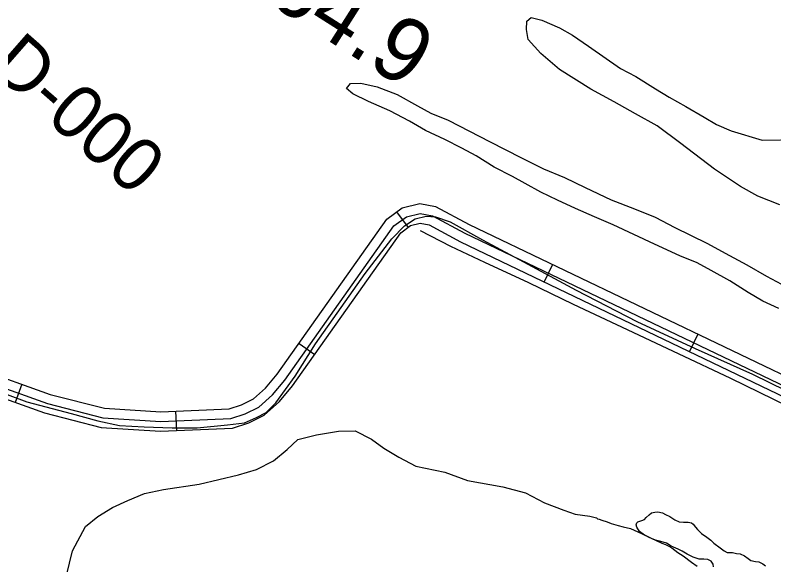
# Model space of a CAD drawing. Extents: x 3361039 to 3398939, y 576572 to 602007.
# Drawn here: x 3386835 to 3388012, y 594802 to 595655 of the extents above; entities that cross this region are included whole.
import ezdxf

# ---------------------------------------------------------------- set-up
doc = ezdxf.new("R2010")
doc.units = 0
for name, color, linetype in [('V-DTCH-CNTR', 7, 'Continuous'), ('V-RIVR-RANG-IDEN', 7, 'Continuous'), ('V-ROAD-CNTR', 7, 'Continuous'), ('V-SITE-VEGE', 7, 'Continuous'), ('V-SURV-IDEN', 7, 'Continuous'), ('V-TOPO-SHOR', 7, 'Continuous')]:
    doc.layers.add(name, color=color, linetype=linetype)

msp = doc.modelspace()

# ---------------------------------------------------------------- linework, layer by layer
at = {"layer": 'V-DTCH-CNTR'}
for points in [[(3386787.3, 595079), (3386852.9, 595054.6), (3386921.8, 595036.6), (3386963.3, 595025), (3386997, 595018.1), (3387035, 595015.7), (3387078.4, 595014.4), (3387117.4, 595014.4), (3387164.5, 595019), (3387190.8, 595022.3), (3387209.7, 595030.3), (3387224.6, 595038.3), (3387239.5, 595053.1), (3387269.6, 595094.5), (3387301.1, 595144.6), (3387340.7, 595201.1), (3387377.9, 595254.2), (3387419.6, 595307.9), (3387439.2, 595328.1), (3387455.6, 595339.1), (3387472.6, 595343.2), (3387487.3, 595341.9), (3387509.8, 595334), (3387560.3, 595306.4), (3387623.6, 595272.3), (3387705.5, 595228.1), (3387799.7, 595179.3), (3387889.9, 595137.7), (3387979.1, 595097.5)], [(3387979.1, 595097.5), (3388056.2, 595060), (3388142.7, 595016.8), (3388245.8, 594973.9), (3388341.5, 594936.1)]]:
    msp.add_lwpolyline(points, dxfattribs=at)
at = {"layer": 'V-ROAD-CNTR'}
for p, q in [((3387426.7, 595349.5), (3387444.7, 595325.5)), ((3387668.8, 595268), (3387655.8, 595240.9)), ((3387894.2, 595159.9), (3387881.2, 595132.8)), ((3387275.6, 595145.5), (3387300.1, 595128.2)), ((3386845.4, 595082.1), (3386835.2, 595053.8)), ((3387083.9, 595040.1), (3387085.2, 595010.2))]:
    msp.add_line(p, q, dxfattribs=at)
for points in [[(3386327.6, 595267.7), (3386889.4, 595066.3), (3386973.4, 595044.7), (3387061, 595039.2), (3387166.9, 595043.6), (3387186, 595049.9), (3387204.7, 595059.1), (3387223.6, 595076.1), (3387241.7, 595097.7), (3387411.8, 595338.4), (3387435.5, 595356.1), (3387462.9, 595362.6), (3387487.4, 595358), (3387539.5, 595330), (3388219.5, 595003.8)], [(3386322.6, 595253.5), (3386885, 595051.9), (3386971.1, 595029.8), (3387060.9, 595024.2), (3387169.6, 595028.7), (3387191.7, 595036), (3387213.2, 595046.5), (3387234.4, 595065.7), (3387253.6, 595088.5), (3387422.7, 595327.8), (3387442, 595342.2), (3387463.3, 595347.3), (3387482.3, 595343.6), (3387532.7, 595316.6), (3388213.1, 594990.3)], [(3386317.5, 595239.4), (3386880.6, 595037.6), (3386968.7, 595015), (3387060.7, 595009.2), (3387172.3, 595013.8), (3387197.4, 595022.1), (3387221.6, 595034), (3387245.2, 595055.2), (3387265.5, 595079.3), (3387433.5, 595317.2), (3387448.5, 595328.3), (3387463.6, 595331.9), (3387477.3, 595329.3), (3387525.9, 595303.2), (3388206.6, 594976.8)]]:
    msp.add_lwpolyline(points, dxfattribs=at)
at = {"layer": 'V-SITE-VEGE'}
for points in [[(3388021.1, 595360.5), (3387987, 595374.1), (3387960.4, 595388.9), (3387919.9, 595416.2), (3387867.6, 595455.6), (3387831, 595483.4), (3387797.5, 595502), (3387764.5, 595520.6), (3387728.1, 595540.1), (3387679.7, 595570.8), (3387650.6, 595595.8), (3387630.7, 595617.5), (3387628.1, 595632.6), (3387628.8, 595645.8), (3387635.6, 595651.3), (3387652.3, 595647.1), (3387679.3, 595635.3), (3387699.5, 595623.8), (3387724.7, 595607.1), (3387774.1, 595572.1), (3387797.7, 595559.7), (3387828.3, 595540.6), (3387849.5, 595527.7), (3387875.6, 595513.4), (3387904.2, 595496.7), (3387922.9, 595485.2), (3387946, 595475.7), (3387994.1, 595460.8), (3388051.6, 595461.9)], [(3388019.9, 595199.8), (3387994.9, 595211.1), (3387972.4, 595224.4), (3387943.9, 595242.5), (3387915, 595258.6), (3387892.9, 595270.5), (3387866, 595281.3), (3387826.8, 595299.7), (3387762.7, 595329.5), (3387733.8, 595341.7), (3387704.4, 595354.9), (3387676.5, 595367.7), (3387650.6, 595380), (3387626.5, 595393.8), (3387606.4, 595404.7), (3387578, 595419.3), (3387550, 595436.5), (3387528, 595448.8), (3387501.5, 595462.1), (3387471.6, 595476.2), (3387446.6, 595490.5), (3387416.2, 595506.6), (3387383.4, 595521.2), (3387359, 595533.1), (3387349.1, 595541.2), (3387355.3, 595549.1), (3387371.4, 595549.3), (3387396.8, 595543.8), (3387427.6, 595532.1), (3387459, 595514.5), (3387480, 595503.1), (3387506.9, 595491.8), (3387572.1, 595458.2), (3387619.6, 595434), (3387654.9, 595416.5), (3387687.2, 595402.9), (3387719.1, 595387.3), (3387759.7, 595368.4), (3387795.9, 595354.3), (3387827.7, 595341.6), (3387858.6, 595325.5), (3387908.1, 595300.9), (3387943.3, 595281.9), (3387970.3, 595267.2), (3388000.7, 595249.6), (3388024.2, 595237.3)], [(3386914.9, 594785.2), (3386924.2, 594823.5), (3386944.2, 594861), (3386963.1, 594876.4), (3386985.9, 594890.5), (3387009.7, 594901.6), (3387035.5, 594912.2), (3387065.3, 594918.5), (3387120.5, 594927.1), (3387181.5, 594941.1), (3387209.3, 594949.4), (3387236, 594963), (3387256.8, 594980.9), (3387273.7, 594996.3), (3387302.5, 595003.5), (3387336.7, 595009.4), (3387362.6, 595009.8), (3387387.8, 594996.9), (3387407.1, 594982.5), (3387430.3, 594968.6), (3387456.9, 594954.8), (3387501.6, 594945.6), (3387537, 594932.4), (3387591.5, 594922.9), (3387626.9, 594913.6), (3387656.4, 594897.8), (3387686.5, 594886.5), (3387703.8, 594880.1), (3387726.5, 594877.4), (3387730.5, 594876.2)], [(3387730.5, 594876.2), (3387736.7, 594874.4), (3387738.5, 594873.1), (3387741.2, 594872.6), (3387745.2, 594871), (3387753.5, 594868.2), (3387759.7, 594865.9), (3387770.4, 594862.6), (3387778.1, 594860.6), (3387789.6, 594857.8), (3387806.5, 594850), (3387822.9, 594842.3), (3387829.3, 594839.4), (3387838.2, 594835.3), (3387843.8, 594833.3), (3387849.2, 594830.7), (3387854, 594827.8), (3387863.1, 594821), (3387871.2, 594815.5), (3387884.1, 594805.8), (3387893.3, 594799.6)]]:
    msp.add_lwpolyline(points, dxfattribs=at)
at = {"layer": 'V-TOPO-SHOR'}
for points in [[(3387463.6, 595320.6), (3387510.3, 595296.4), (3387563, 595271.7), (3387631.4, 595239.9), (3387700.7, 595206.6), (3387768.2, 595174.8), (3387863.6, 595129.7), (3387944.8, 595091.7), (3388033.9, 595048), (3388121.9, 595008.6), (3388204.1, 594971.2), (3388222.8, 594958.7), (3388241.1, 594944.8), (3388264.7, 594933.9), (3388295.7, 594921.1), (3388326.6, 594909.8), (3388339, 594903.1), (3388359.7, 594887.3), (3388395.7, 594861.9), (3388432, 594830.2)], [(3387877.4, 594818.3), (3387869.8, 594822.8), (3387863.6, 594826), (3387852.8, 594830.7), (3387845.3, 594835.5), (3387836.8, 594838), (3387828.6, 594839.8), (3387818.5, 594843.9), (3387809.3, 594849), (3387803.7, 594853.4), (3387799.4, 594859.9), (3387798.3, 594863.8), (3387799.3, 594866.7), (3387800.9, 594868.4), (3387807.3, 594870.4), (3387811.2, 594872.1), (3387814.1, 594875.1), (3387818.6, 594879.4), (3387822.2, 594882.3), (3387827.3, 594883.4), (3387832.2, 594884.1), (3387839.1, 594882.2), (3387844, 594880), (3387850.5, 594876.9), (3387858.4, 594871.4), (3387865.3, 594868.3), (3387871.8, 594867.7), (3387879.3, 594867.8), (3387884.5, 594866.9), (3387886.8, 594865), (3387890.5, 594860.2), (3387893.8, 594856.6), (3387900, 594850.2), (3387907.9, 594844.8), (3387914.2, 594840), (3387918.8, 594835.2), (3387928.7, 594827.8), (3387934.9, 594823.1), (3387939.8, 594820.8), (3387944.4, 594820.9), (3387948, 594820.6), (3387954.2, 594819.4), (3387960, 594818.5), (3387966.6, 594815.4), (3387972.2, 594811.5), (3387976.4, 594808.3), (3387983.6, 594806.8), (3387988.8, 594806.2), (3387995.1, 594803.1), (3387999.3, 594800.2)], [(3387918.7, 594798.7), (3387918, 594802.6), (3387914.6, 594807.2), (3387909.4, 594810), (3387903.2, 594810.2), (3387896.4, 594810.5), (3387886.9, 594813.6), (3387877.4, 594818.3)]]:
    msp.add_lwpolyline(points, dxfattribs=at)

# ---------------------------------------------------------------- texts
at = {"layer": 'V-RIVR-RANG-IDEN'}
msp.add_text('D-000', height=83, rotation=318.8573, dxfattribs=at).set_placement((3386792.4, 595570.9))
at = {"layer": 'V-SURV-IDEN'}
msp.add_text('2519+64.9', height=100, rotation=327.6025, dxfattribs=at).set_placement((3386904.2, 595879.5))

doc.saveas('drawing.dxf')
